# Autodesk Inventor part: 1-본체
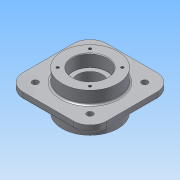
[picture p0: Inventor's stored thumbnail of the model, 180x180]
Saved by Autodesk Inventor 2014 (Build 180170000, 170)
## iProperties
Created: 2015-09
Part Number: 1-본체
Material: 알루미늄 6061
Document SubType Name: Modeling
Designer: study
Density: 2.71 g/cm^3
Appearance: 알루미늄 - 평지
Mass: 1467.19 g
Surface Area: 804.168 cm^2
Volume: 541.4 cm^3
Author: study
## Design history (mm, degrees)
sketch "스케치1"
  geometry: L1 (-75, 75)-(75, 75); L2 (75, 75)-(75, -75); L3 (75, -75)-(-75, -75); L4 (-75, -75)-(-75, 75); L5 (-75, 75)-(75, -75); L6 (75, 75)-(-75, -75); 1 further point
  constraints: 12 end point, 2 midpoint, 2 parallel, 1 horizontal, 1 perpendicular
  dimensions: "d0" = 150 distance of L1.start L1.end; "d1" = 150 distance of L3.end L1.start
extrude "돌출1" new body sketch "스케치1" distance "d2" = 12; taper "d3" = 0 deg
sketch "스케치2"
  geometry: C1 r 50 at (0, 0); 1 further point
  constraints: 1 centre point, 1 coincident
  dimensions: "d5" = 100 diameter of C1
extrude "돌출2" join sketch "스케치2" distance "d6" = 23; taper "d7" = 0 deg
sketch "스케치3"
  geometry: C1 r 50 at (0, 0); 1 further point
  constraints: 1 centre point, 1 coincident
  dimensions: "d8" = 100 diameter of C1
extrude "돌출3" join sketch "스케치3" distance "d9" = 35; taper "d10" = 0 deg
sketch "스케치4"
  geometry: C1 r 50 at (0, 0) reference
hole "구멍1" sketch "스케치4" at (0, 0) diameter "d16" = 45; stored, may be unused: countersink angle "d20" = 90 deg, drill point angle "d22" = 118 deg; dims "d17" = 6, "d18" = 62, "d19" = 22, "d21" = 8
hole "구멍2" diameter "d25" = 45; stored, may be unused: countersink angle "d29" = 90 deg, drill point angle "d31" = 118 deg; dims "d23" = 10, "d24" = 10, "d26" = 6, "d27" = 62, "d28" = 22, "d30" = 8
sketch "스케치7"
  geometry: C1 r 31 at (0, 0) reference; C2 r 50 at (0, 0) reference; A1 r 41 centre (0, 0) between (-28.991, 28.991) and (28.991, 28.991); 2 further points
  constraints: 4 point on circle, 2 vertical alignment, 1 centre point, 1 coincident, 1 horizontal alignment
  dimensions: "d51" = 82 diameter of A1; "d53" = 90 deg dimension on C1.centre A1.start A1.end
hole "구멍5" sketch "스케치7" at (-28.991, 28.991), (28.991, 28.991), (-28.991, -28.991), (28.991, -28.991) diameter "d54" = 4.917; stored, may be unused: countersink angle "d58" = 90 deg, drill point angle "d60" = 118 deg; dims "d55" = 10, "d56" = 62, "d57" = 22, "d59" = 13
sketch "스케치9"
  geometry: C1 r 50 at (0, 0) reference; C2 r 10 at (-49, 49); C3 r 10 at (49, 49); C4 r 10 at (-49, -49); C5 r 10 at (49, -49)
  constraints: 4 centre point, 2 horizontal alignment, 1 equal radius
  dimensions: "d62" = 20 diameter of C2; "d63" = 49 horizontal distance of C1.centre C2.centre; "d64" = 98 distance of C3.centre C2.centre; "d65" = 20 diameter of C5; "d66" = 20 diameter of C4; "d67" = 49 horizontal distance of C1.centre C4.centre; "d68" = 98 distance of C5.centre C4.centre; "d69" = 49 horizontal distance of C1.centre C2.centre; "d70" = 98 distance of C4.centre C2.centre
extrude "돌출5" join sketch "스케치9" distance "d71" = 5; taper "d72" = 0 deg
sketch "스케치10"
  geometry: C1 r 10 at (0, 0) reference; 1 further point
sketch "스케치11"
  geometry: L1 (75, 75)-(-75, 75) reference; L2 (-75, 75)-(-75, -75) reference; L3 (-75, -75)-(75, -75) reference; L4 (75, -75)-(75, 75) reference; C1 r 10 at (-49, -49) reference; C2 r 10 at (-49, 49) reference; C3 r 10 at (49, 49) reference; C4 r 10 at (49, -49) reference; C5 r 50 at (0, 0) reference
hole "구멍7" sketch "스케치10" diameter "d80" = 11; stored, may be unused: countersink angle "d84" = 90 deg, drill point angle "d86" = 0 deg; dims "d81" = 10, "d82" = 62, "d83" = 22, "d85" = 13
sketch "스케치12"
  geometry: C1 r 10 at (0, 0) reference; 1 further point
hole "구멍8" sketch "스케치12" at (0, 0) diameter "d87" = 11; stored, may be unused: countersink angle "d91" = 90 deg, drill point angle "d93" = 0 deg; dims "d88" = 10, "d89" = 62, "d90" = 22, "d92" = 13
sketch "스케치13"
  geometry: C1 r 10 at (0, 0) reference; 1 further point
hole "구멍9" sketch "스케치13" at (0, 0) diameter "d94" = 11; stored, may be unused: countersink angle "d98" = 90 deg, drill point angle "d100" = 0 deg; dims "d95" = 10, "d96" = 62, "d97" = 22, "d99" = 13
sketch "스케치14"
  geometry: C1 r 10 at (0, 0) reference; 1 further point
hole "구멍10" sketch "스케치14" at (0, 0) diameter "d101" = 11; stored, may be unused: countersink angle "d105" = 90 deg, drill point angle "d107" = 0 deg; dims "d102" = 10, "d103" = 62, "d104" = 22, "d106" = 13
fillet "모깎기2" dims "d108" = 30
fillet "모깎기3" dims "d109" = 3, "d110" = 0.3
chamfer "모따기1" distance "d111" = 1; stored, may be unused: second distance "d112" = 2, angle "d113" = 45 deg
fillet "모깎기4" dims "d114" = 3
sketch "스케치16"
  geometry: C1 r 53 at (0, 0) reference; 1 further point
  constraints: 1 vertical alignment, 1 other
  dimensions: "d115" = 65 distance of C1.centre point (0, 65)
feature "엠보싱1" sketch "스케치16" dims "d0" = 150, "d1" = 150, "d116" = 1, "d117" = 0
node "솔리드1"
mirror "대칭2"
